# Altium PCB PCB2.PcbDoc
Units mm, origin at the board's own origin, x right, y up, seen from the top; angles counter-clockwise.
Board outline 233.81 x 149.73 mm, 2 copper layers (Top Layer, Bottom Layer); 51 components, 27 nets, 122 pads, 0 vias.
Unrouted connection lines stored in the file: 1.
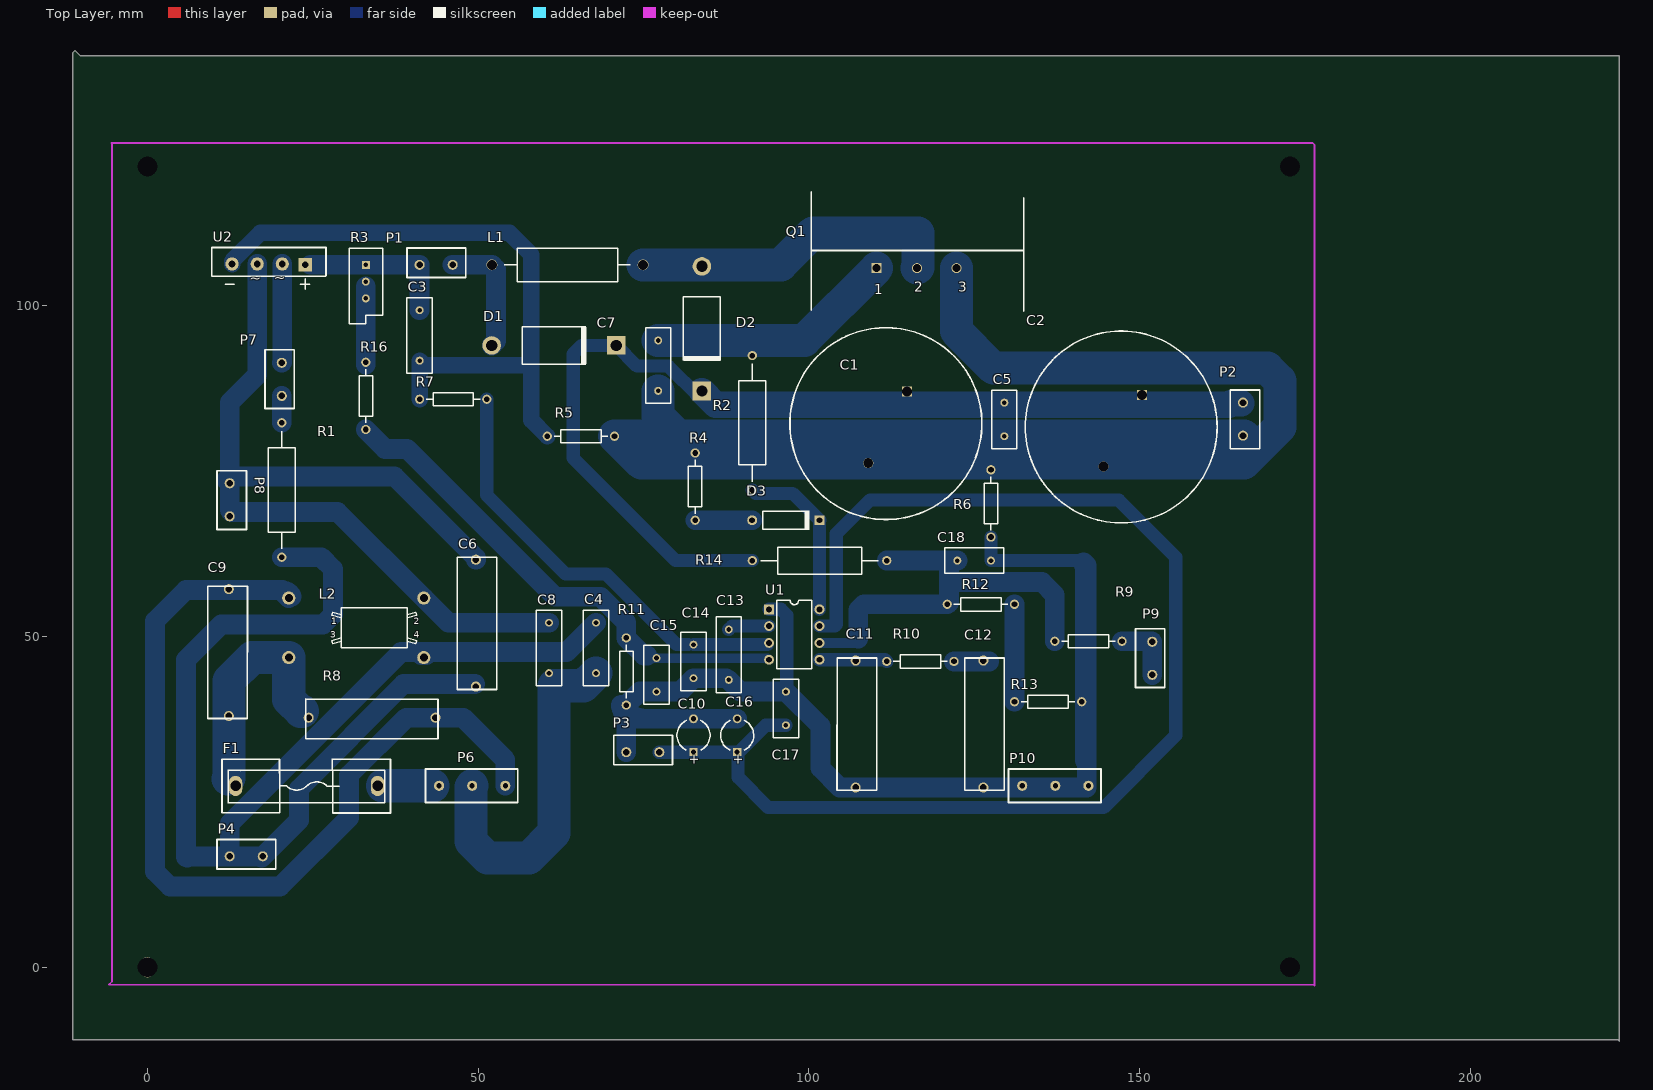
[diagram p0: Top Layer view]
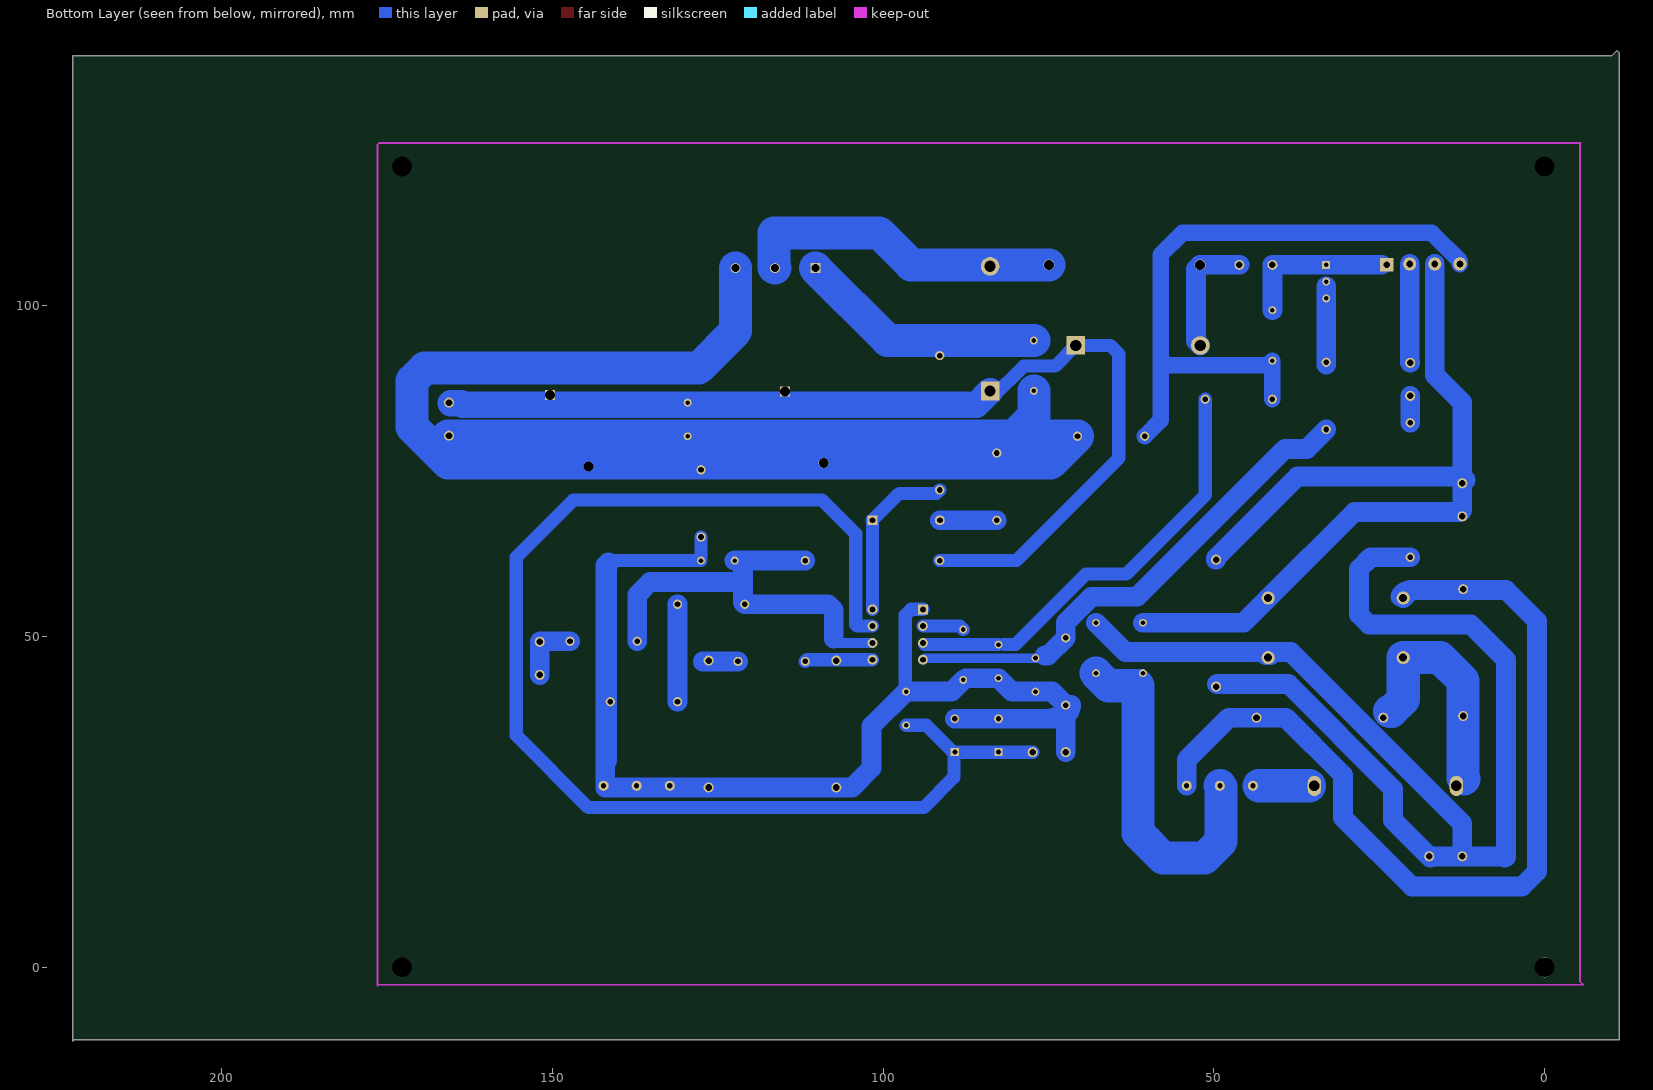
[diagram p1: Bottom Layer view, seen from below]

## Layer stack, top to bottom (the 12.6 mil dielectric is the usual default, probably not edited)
Top Layer: signal copper 0.0356
Dielectric: dielectric 0.32, FR-4, Dk 4.8
Bottom Layer: signal copper 0.0356

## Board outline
3.302,137.795 222.504,137.795 222.504,-11.176 222.25,-10.922 -11.303,-10.922 -11.303,138.176 -10.922,138.557 -10.16,137.795 2.921,137.795

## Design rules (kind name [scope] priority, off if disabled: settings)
Clearance [All] p1: gap=0.254
PolygonConnect [All] p1: connectstyle=Relief reliefconductorwidth=0.254 reliefentries=4 polygonreliefangle="90 Angle"
RoutingVias [All] p1: holewidth=0.711 width=1.27 viastyle="Through Hole" minholewidth=0.711 minwidth=1.27 maxholewidth=0.711 maxwidth=1.27
SilkscreenOverComponentPads [All] p1: minsilkscreentomaskgap=0.254
SolderMaskExpansion [All] p1: expansion=0.102
TestPointUsage [All] p1: valid=0 allowmultiple=FALSE
Testpoint [All] p1: side=15 testpointundercomponent=TRUE minsize=1.016 maxsize=2.54 preferedsize=1.524 minholesize=0 maxholesize=1.016 preferedholesize=0.813 testpointgrid=0.025 style=1023 order=0123456789
Width [All] p1: maxlimit=10 minlimit=0.254 preferedwidth=0.254
23 further rules are at their usual default settings.

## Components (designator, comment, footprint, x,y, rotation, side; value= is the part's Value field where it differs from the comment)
C1 "Cap Pol1" dianrong 111.76,82.296 r270 top
C2 "Cap Pol1" dianrong 147.32,81.788 r270 top
C3 "Cap" RAD-0.3 41.148,95.504 r90 top
C4 "Cap" RAD-0.3 67.818,48.26 r270 top
C5 "Cap" RAD-0.2 129.54,82.804 r270 top
C6 "Cap" CBB-CAP 52.832,61.976 r180 top
C7 "Cap" RAD-0.3 77.216,90.932 r90 top
C8 "Cap" RAD-0.3 60.706,48.26 r90 top
C9 "Cap" CBB-CAP 9.144,37.592 r0 top
C10 "Cap Pol1" CAPPR5-5x5 82.55,35.052 r90 top
C11 "Cap" CBB-CAP 110.236,46.736 r180 top
C12 "Cap" CBB-CAP 129.54,46.736 r180 top
C13 "Cap" RAD-0.3 87.884,47.244 r90 top
C14 "Cap" RAD-0.2 82.55,46.228 r90 top
C15 "Cap" RAD-0.2 76.962,44.196 r90 top
C16 "" CAPPR5-5x5 89.154,35.052 r90 top
C17 "Cap" RAD-0.2 96.52,39.116 r270 top
C18 "Cap" RAD-0.2 124.968,61.468 r180 top
D1 "IN4001" DIO18.84-9.6x5.6 61.468,93.98 r0 top
D2 "IN4001" DIO18.84-9.6x5.6 83.82,96.52 r270 top
D3 "1N5230" DIO10.2-7x2.7 96.52,67.564 r0 top
F1 "Fuse 2" fuse 34.798,27.432 r180 top
L1 "Inductor Iron" AXIAL-0.9 63.5,106.172 r0 top
L2 "Trans" TRANS 34.29,51.308 r0 top
P1 "Header 2H" 2KOUZUOZI 41.148,106.172 r0 top
P2 "Header 2" 2KOUZUOZI 165.608,85.344 r270 top
P3 "+12v 输入" 2KOUZUOZI 72.39,32.512 r0 top
P4 "Header 2H" 2KOUZUOZI 12.446,16.764 r0 top
P6 "Header 3" 3KOUZUOZI 54.102,27.432 r180 top
P7 "Header 2H" 2KOUZUOZI 20.32,86.36 r90 top
P8 "Header 2H" 2KOUZUOZI 12.446,73.152 r270 top
P9 "Header 2" 2KOUZUOZI 151.892,44.196 r90 top
P10 "Header 3" 3KOUZUOZI 142.24,27.432 r180 top
Q1 "NMOS-2" kaiguanguan 110.236,105.664 r0 top
R1 "Res2" AXIAL-0.8 20.32,72.136 r90 top
R2 "Res2" AXIAL-0.8 91.44,82.296 r270 top
R3 "RPot" VR5 33.02,103.632 r270 top
R4 "Res2" AXIAL-0.4 82.804,72.644 r270 top
R5 "Res2" AXIAL-0.4 65.532,80.264 r0 top
R6 "Res2" AXIAL-0.4 127.508,70.104 r90 top
R7 "Res2" AXIAL-0.4 46.228,85.852 r0 top
R8 "Res2" CBB-CAP 43.942,34.544 r90 top
R9 "Res2" AXIAL-0.4 142.24,49.276 r0 top
R10 "Res2" AXIAL-0.4 116.84,46.228 r180 top
R11 "Res2" AXIAL-0.4 72.39,44.704 r90 top
R12 "Res2" AXIAL-0.4 125.984,54.864 r180 top
R13 "Res2" AXIAL-0.4 136.144,40.132 r180 top
R14 "Res2" AXIAL-0.8 101.6,61.468 r0 top
R16 "Res2" AXIAL-0.4 33.02,86.36 r90 top
U1 "UC28019" DIP-8 97.79,50.292 r270 top
U2 "Brige1" Brige-3A 23.876,106.172 r180 top

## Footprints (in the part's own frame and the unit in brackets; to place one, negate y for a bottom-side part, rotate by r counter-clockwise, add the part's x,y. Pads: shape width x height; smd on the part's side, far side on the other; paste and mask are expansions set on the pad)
2KOUZUOZI [mil]
  round 60 hole 39.37: 1(0,0) 2(196.85,0)
  silkscreen extent -75,-75 275,100
3KOUZUOZI [mil]
  round 60 hole 30: 1(0,0) 2(196.85,0) 3(393.7,0)
  silkscreen extent -75,-100 475,100
AXIAL-0.4 [mm] "Resistor; 2 Leads"
  round 1.4 hole 0.85: 1(-5.08,0) 2(5.08,0)
  silkscreen extent -4.06,-1.02 4.06,1.02
AXIAL-0.8 [mm] "Axial Device, Thru-Hole; 2 Leads; 0.8 in Pin Spacing"
  round 1.4 hole 0.85: 1(-10.16,0) 2(10.16,0)
  silkscreen extent -8.89,-2.03 8.89,2.03
AXIAL-0.9 [mm] "Magnetic-Core Inductor; 2 Leads"
  round 1.65 hole 1.5: 1(-11.43,0) 2(11.43,0)
  silkscreen extent -9.53,-2.54 9.53,2.54
Brige-3A [mm] "ARM Brige"
  rect 2x2 hole 1: 1(0,0)
  round 2 hole 1: 2(3.475,-0.125) 3(7.275,-0.125) 4(11.075,-0.125)
  silkscreen extent -3.12,-2.62 14.12,3.67
CAPPR5-5x5 [mm] "Capacitor, Electrolytic, Radial; Body 5 x 5 mm (Dia.xH typ); Pin Spacing 5 mm (typ)"
  rect 1.25x1.25 hole 0.75: 1(-2.5,0)
  round 1.35 hole 0.8: 2(2.5,0)
  silkscreen extent -2.26,-2.5 2.27,2.5
CBB-CAP [mil]
  round 60 hole 39.37: 1(125,770) 2(125,15)
  silkscreen extent 0,0 236,787
dianrong [mil]
  rect 60x60 hole 59.06: 1(-185,120)
  round 60 hole 59.06: 2(240,-110)
  silkscreen extent -566,-576 576,566
DIO10.2-7x2.7 [mm] "Diode, Axial; Body 7 x 2.7 mm (LxDia. max), Lead Dia. 0.53 mm (max)"
  round 1.5 hole 0.9: 1(-5.1,0)
  rect 1.5x1.5 hole 0.9: 2(5.1,0)
  silkscreen extent -3.5,-1.35 3.6,1.35
DIO18.84-9.6x5.6 [mm] "Diode, Axial; Body 9.5 x 5.6 mm (LxDia. max), Lead Dia. 1.32 mm (max)"
  round 2.8 hole 1.7: 1(-9.42,0)
  rect 2.8x2.8 hole 1.7: 2(9.42,0)
  silkscreen extent -4.8,-2.8 4.9,2.8
DIP-8 [mm] "DIP; 8 Leads; Row Spacing 7.62 mm; Pitch 2.54 mm"
  rect 1.5x1.5 hole 0.9: 1(-3.81,-3.81)
  round 1.5 hole 0.9: 2(-1.27,-3.81) 3(1.27,-3.81) 4(3.81,-3.81) 5(3.81,3.81) 6(1.27,3.81) 7(-1.27,3.81) 8(-3.81,3.81)
  silkscreen extent -5.15,-2.65 5.15,2.65
fuse [mil]
  oval 80x120 hole 62.99: 1(0,1) 1(1370,1080) 2(845,1) 2(1370,1080)
  silkscreen extent -77,-158 925,162
kaiguanguan [mil]
  rect 60x60 hole 47.24: 1(0,0)
  round 60 hole 47.24: 2(240,0) 3(475,0)
  silkscreen extent -390,-255 875,455
RAD-0.2 [mm] "Jumper Wire; 2 Leads"
  round 1.2 hole 0.7: 1(-2.54,0) 2(2.54,0)
  silkscreen extent -4.44,-1.91 4.44,1.91
RAD-0.3 [mm] "Capacitor; 2 Leads"
  round 1.2 hole 0.7: 1(-3.81,0) 2(3.81,0)
  silkscreen extent -5.71,-1.91 5.71,1.91
TRANS [mm] "Transformer; 4 Leads"
  round 2 hole 1.2: 1(-12.912,4.5) 2(7.5,4.5) 3(-12.912,-4.5) 4(7.5,-4.5)
  silkscreen extent -6.4,-3 6.4,3
VR5 [mm] "Potentiometer; 3 Leads"
  rect 1.2x1.2 hole 0.7: 1(-2.54,0)
  round 1.2 hole 0.7: 2(0,0) 3(2.54,0)
  silkscreen extent -5.08,-2.54 6.35,2.54

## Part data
C1 C2 C10: "Polarized Capacitor (Radial)"
C3 C4 C5 C6 C7 C8 C9 C11 C12 C13 C14 C15 C17 C18: "Capacitor"
C16: library part "Cap Pol1", "Polarized Capacitor (Radial)"
D1 D2: library part Diode, "Default Diode"
F1: "Fuse"
L1: "Magnetic-Core Inductor"
L2: "Transformer"
P1 P4 P7 P8: "Header, 2-Pin, Right Angle"
P2 P9: "Header, 2-Pin"
P3: library part "Header 2H", "Header, 2-Pin, Right Angle"
P6 P10: "Header, 3-Pin"
Q1: "N-Channel Power MOSFET"
R1 R2 R4 R5 R6 R7 R8 R9 R10 R11 R12 R13 R14 R16: "Resistor"
R3: "Potentiometer"
U1: library part UCC28019
U2: "Full Wave Diode Bridge"

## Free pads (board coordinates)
  round 1.524 hole 3: 0(0,0) 1(172.72,0) 2(172.72,121.031) 3(0,121.031)

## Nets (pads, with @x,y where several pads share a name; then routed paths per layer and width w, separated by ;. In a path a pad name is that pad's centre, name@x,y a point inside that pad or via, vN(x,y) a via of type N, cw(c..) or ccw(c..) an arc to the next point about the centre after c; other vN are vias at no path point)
DAC7614OUT: P9.1 P9.2 R9.2 | length 9.6
  Bottom Layer w3: R9.2 151.812,49.276 P9.2 P9.1
GND: C1.2 C2.2 C4.2 C5.2 C7.1 C8.1 P2.2 P6.2 Q1.3 R4.1 R5.2 R6.2 | length 333.4
  Bottom Layer w5: P6.2 48.895,27.225 48.895,19.05 51.435,16.51 57.658,16.51 61.468,20.32 61.468,42.554 65.922,42.554 C4.2 ; C7.1 77.216,83.312 80.264,80.264 ; Q1.3 122.301,96.139 127.889,90.551 169.291,90.551 171.196,88.646 171.196,81.661 165.735,76.2 ; 80.264,80.264 C5.2 165.735,80.264 165.735,76.2 ; 80.264,80.264 R5.2 74.676,76.2 85.471,76.2 C1.2 165.735,76.2
GNDD: C10.2 C11.1 C12.1 C13.1 C14.1 C15.1 C16.2 C17.1 C18.1 P3.1 P10.1 P10.2 P10.3 R6.1 R11.1 R13.1 U1.1 | length 207.9
  Bottom Layer w2: U1.1 95.758,54.102 96.647,53.213 96.647,41.783 C17.1 ; R6.1 C18.1 141.224,61.468 141.478,61.214 141.478,60.938
  Bottom Layer w3: 71.59,39.624 ccw(c73.338,39.624) 72.102,38.388 ; 71.824,39.058 ccw(c75.461,42.695) 75.461,37.552 ; P3.1 72.39,38.1 ; C13.1@87.503,43.688 C14.1 80.518,41.656 C15.1 74.422,41.656 R11.1 72.39,38.1 ; C13.1 89.662,41.656 C17.1 101.727,36.449 101.727,30.099 104.648,27.178 141.986,27.178 141.986,30.988 ; C16.2 C10.2 72.938,37.552 72.39,38.1 ; 141.478,60.938 141.732,60.833 141.732,31.242 141.986,30.988 ; 141.478,61.214 141.986,60.706 141.986,30.988
NetC1_1: C1.1 C2.1 C5.1 D1.2 D2.2 P2.1 R14.1 | length 154.9
  Bottom Layer w2: D2.2@83.82,86.233 83.414,86.233 78.771,90.876 73.992,90.876 D1.2 65.659,93.98 64.389,92.71 64.389,76.962 79.883,61.468 R14.1
  Bottom Layer w4: D2.2 85.902,85.018 163.531,85.018 163.766,85.253 P2.1@165.354,85.253
NetC3_1: C3.1 R5.1 R7.1 U2.4 | length 103.3
  Bottom Layer w2.5: U2.4 12.801,106.745 17.054,110.998 54.737,110.998 58.039,107.696 58.039,91.948 ; R7.1 C3.1 41.866,90.976 57.067,90.976 58.039,91.948 ; 58.039,94.615 58.039,91.948 ; R5.1 58.039,82.677 58.039,91.948
NetC3_2: C3.2 P1.1 R3.1 U2.1 | length 23
  Bottom Layer w3: U2.1@24.638,106.172 R3.1 P1.1@40.767,106.172 ; C3.2 P1.1
NetC4_1: C4.1 C6.1 L2.4 P4.1 P4.2 R1.1 | length 202.8
  Bottom Layer w3: P4.2@17.237,16.555 17.029,16.764 P4.1 ; P4.2 22.902,22.22 22.902,26.966 38.735,42.799 C6.1@49.53,42.799 ; R1.1 26.289,61.976 28.067,60.198 28.067,53.34 26.543,51.816 11.176,51.816 5.842,46.482 5.842,16.659 6.037,16.578 6.223,16.764 P4.1 ; 41.025,47.625 cw(c41.025,46.043) L2.4@42.144,47.162 ; L2.4@41.436,47.162 cw(c42.555,46.043) 42.555,47.625 ; C4.1 63.373,47.625 38.354,47.625 12.446,21.717 P4.1
NetC6_2: C6.2 C8.2 L2.2 P8.1 P8.2 U2.3 | length 137.1
  Bottom Layer w3: P8.1@11.924,73.674 cw(c13.117,72.481) 13.117,74.168 ; P8.1 12.446,69.088 12.7,68.834 28.764,68.834 L2.2 45.528,52.07 C8.2 ; U2.3 16.601,89.499 12.446,85.344 12.446,74.168 37.338,74.168 49.657,61.849 C6.2
NetC7_2: C7.2 Q1.1 R2.1 | length 37.5
  Bottom Layer w5: C7.2 99.314,94.742 Q1.1
NetC9_1: C9.1 L2.1 P6.1 R8.2 | length 139.7
  Bottom Layer w3: 19.652,57.023 cw(c19.652,54.082) L2.1@21.732,56.162 ; L2.1 20.163,57.023 ; L2.1@21.815,56.051 ccw(c20.163,55.133) 20.163,57.023 ; P6.1 54.102,31.369 47.752,37.719 R8.2 39.133,37.719 30.48,29.066 30.48,22.606 20.066,12.192 3.429,12.192 1.143,14.478 1.143,52.324 5.842,57.023 20.163,57.023
NetC9_2: C9.2 F1.2@13.335,27.407 L2.3 R8.1 | length 34.5
  Bottom Layer w5: 12.192,28.448 12.319,28.575 C9.2 12.319,43.307 15.82,46.808 L2.3 21.378,40.471 23.154,38.695 23.408,38.695
NetC10_1: C10.1 C16.1 C17.2 P3.2 U1.7 | length 197.6
  Bottom Layer w2: P3.2 C16.1@89.154,32.512 ; C17.2 93.472,36.576 89.448,32.552 C16.1 89.281,32.425 89.281,28.702 93.853,24.13 144.526,24.13 155.448,35.052 155.448,61.976 146.812,70.612 109.22,70.612 104.14,65.532 104.14,51.816 103.886,51.562 U1.7
NetC11_2: C11.2 R10.2 U1.5 | length 10.3
  Bottom Layer w2: U1.5 111.506,46.482 R10.2
NetC12_2: C12.2 R10.1 | length 8.6
  Bottom Layer w3: 125.222,46.228 R10.1 127.254,46.228
NetC13_2: C13.2 U1.2 | length 6.3
  Bottom Layer w2: C13.2 88.392,51.562 U1.2
NetC14_2: C14.2 R7.2 U1.3 | length 66.6
  Bottom Layer w1: 81.788,48.768 C14.2 ; U1.3@93.726,48.768 U1.3
  Bottom Layer w2: R7.2 51.308,71.374 63.246,59.436 69.342,59.436 80.01,48.768 81.788,48.768 ; C14.2 U1.3@93.726,48.768
NetC15_2: C15.2 R11.2 R16.1 U1.4 | length 76.7
  Bottom Layer w1.5: 75.565,47.117 75.946,46.736 C15.2 76.99,46.708 93.754,46.708 U1.4
  Bottom Layer w3: R16.1 35.941,78.359 39.243,78.359 61.595,56.007 68.483,56.007 72.39,52.1 R11.2 75.057,47.117 75.565,47.117
NetC18_2: C18.2 R9.1 R12.2 R14.2 U1.6 | length 65.5
  Bottom Layer w1.5: U1.6 106.807,49.022 107.442,49.657
  Bottom Layer w3: 107.442,49.657 107.442,53.975 108.331,54.864 R12.2 121.158,55.118 121.158,58.293 ; R14.2 121.158,61.468 ; C18.2 121.158,61.468 ; R9.1 137.16,56.261 135.207,58.214 121.237,58.214 121.158,58.293 ; 121.158,58.293 121.158,61.468
NetD1_1: D1.1 L1.1 P1.2 | length 18.6
  Bottom Layer w3: P1.2 L1.1 52.705,105.537 52.705,94.637 D1.1
NetD2_1: D2.1 L1.2 Q1.2 | length 48.9
  Bottom Layer w5: L1.2 95.758,106.172 100.584,110.998 116.459,110.998 116.459,105.791 Q1.2
NetD3_1: D3.1 R4.2 | length 8.6
  Bottom Layer w3: R4.2 D3.1
NetD3_2: D3.2 R2.2 U1.8 | length 26.8
  Bottom Layer w2: R2.2 91.948,71.628 97.516,71.628 D3.2@101.6,67.544 ; U1.8 101.6,63.627 ; 101.6,64.897 101.6,63.627 ; D3.2 D3.2@101.6,67.544 ; 101.6,63.627 D3.2@101.6,67.544
NetF1_1: F1.1@34.798,27.407 P6.3 | length 7.6
  Bottom Layer w5: F1.1@35.56,27.432 43.18,27.432
NetP7_1: P7.1 R1.2 | length 4.1
  Bottom Layer w3: R1.2 P7.1
NetP7_2: P7.2 U2.2 | length 15
  Bottom Layer w3: P7.2 20.401,91.441 U2.2
NetR3_2: R3.2 R3.3 R16.2 | length 11.8
  Bottom Layer w3: R16.2@33.02,91.059 33.02,102.87
NetR12_1: R12.1 R13.2 | length 14.7
  Bottom Layer w3: R13.2 R12.1
pads on no net: F1.1@0,0 F1.2@0,0

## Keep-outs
Keep-Out Layer:
  lines w0.254: -5.461,124.587 176.149,124.587 176.403,124.333 176.403,-2.794 176.276,-2.667 -5.842,-2.667 -5.334,-2.159 -5.334,124.587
